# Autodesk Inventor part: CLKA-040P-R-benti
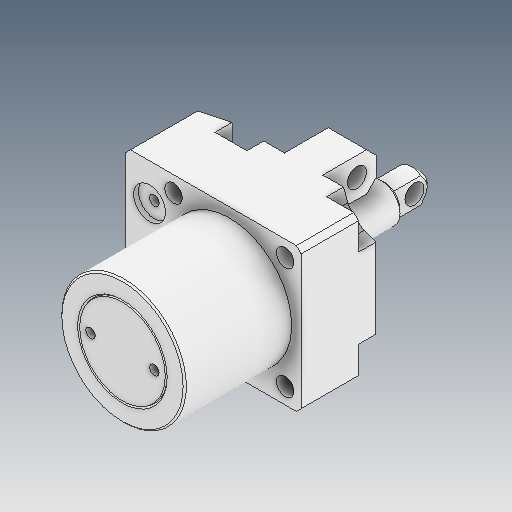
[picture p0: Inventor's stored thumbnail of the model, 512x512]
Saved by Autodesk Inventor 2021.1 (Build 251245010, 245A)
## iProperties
Created: 2021-06
Part Number: CLKA-040P-R-benti
Material: Ogólny
Document SubType Name: Modeling
Designer: user
Density: 1 g/cm^3
Appearance: Domyślna
Author: user
Revision Number: ÈÎºÎ
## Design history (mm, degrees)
feature "Í¹Ì¨-À­Éì6"
node "Bryła1"
